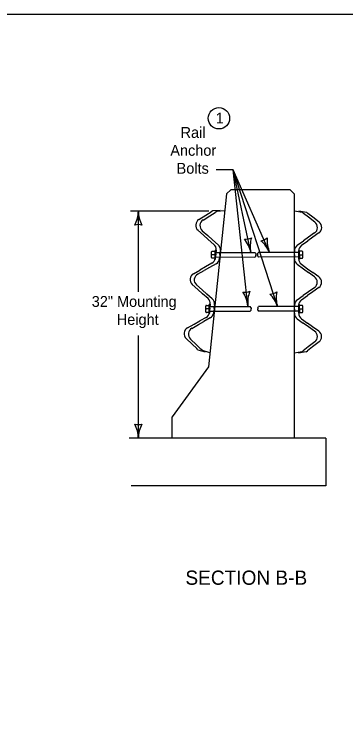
# Model space of a CAD drawing. Extents: x 10028 to 81668, y 3581 to 11018.
# Drawn here: x 14485 to 14950, y 8948 to 9944 of the extents above; entities that cross this region are included whole.
import ezdxf

# ---------------------------------------------------------------- set-up
doc = ezdxf.new("R2010")
doc.units = 0
for name, color, linetype in [('dsnCellsNorthArrow', 7, 'Continuous'), ('dsnTextTabulation', 7, 'Continuous'), ('Level 9', 7, 'Continuous'), ('SheetBorder', 7, 'Continuous')]:
    doc.layers.add(name, color=color, linetype=linetype)

msp = doc.modelspace()

# ---------------------------------------------------------------- linework, layer by layer
at = {"layer": 'dsnCellsNorthArrow'}
for p, q in [((14788.88, 9697.25), (14782.39, 9691.57)), ((14872.02, 9697.25), (14788.88, 9697.25)), ((14877.77, 9691.27), (14872.02, 9697.25)), ((14782.39, 9691.57), (14757.16, 9448.63)), ((14877.77, 9348.63), (14877.77, 9691.27)), ((14757.16, 9448.63), (14706.58, 9378.63)), ((14706.58, 9348.63), (14706.58, 9378.63))]:
    msp.add_line(p, q, dxfattribs=at)
at = {"layer": 'dsnTextTabulation'}
for p, q in [((14791.77, 9725.56), (14768.17, 9725.56)), ((14812.49, 9534.46), (14791.77, 9725.56)), ((14816.68, 9609.51), (14791.77, 9725.56)), ((14854.17, 9533.33), (14791.77, 9725.56)), ((14843.09, 9609.5), (14791.77, 9725.56)), ((14647.84, 9667.77), (14757.73, 9667.77)), ((14753.37, 9661.57), (14760.95, 9666.28)), ((14763.19, 9667.67), (14760.95, 9666.28)), ((14773.91, 9668.41), (14763.19, 9667.67)), ((14769.16, 9667.03), (14766.92, 9665.64)), ((14779.87, 9667.77), (14769.16, 9667.03)), ((14878.05, 9667.77), (14888.63, 9665.89)), ((14884.05, 9667.77), (14894.63, 9665.89)), ((14658.91, 9554.01), (14658.91, 9661.87)), ((14743.84, 9655.65), (14753.37, 9661.57)), ((14749.8, 9655.01), (14759.34, 9660.93)), ((14759.34, 9660.93), (14766.92, 9665.64)), ((14888.63, 9665.89), (14890.71, 9664.26)), ((14897.74, 9658.78), (14890.71, 9664.26)), ((14894.63, 9665.89), (14896.71, 9664.26)), ((14903.74, 9658.78), (14896.71, 9664.26)), ((14906.59, 9651.87), (14897.74, 9658.78)), ((14912.59, 9651.87), (14903.74, 9658.78)), ((14742.56, 9640.61), (14750.31, 9633.75)), ((14748.53, 9639.96), (14756.28, 9633.1)), ((14906.25, 9636.78), (14897.81, 9630.78)), ((14912.25, 9636.78), (14903.81, 9630.78)), ((14750.31, 9633.75), (14756.98, 9627.84)), ((14756.28, 9633.1), (14762.95, 9627.2)), ((14764.94, 9620.79), (14756.98, 9627.84)), ((14770.91, 9620.15), (14762.95, 9627.2)), ((14897.81, 9630.78), (14890.55, 9625.62)), ((14903.81, 9630.78), (14896.55, 9625.62)), ((14881.88, 9619.47), (14890.55, 9625.62)), ((14887.88, 9619.47), (14896.55, 9625.62)), ((14767.5, 9607.28), (14767.11, 9603.54)), ((14767.48, 9607.14), (14767.89, 9611.01)), ((14768.07, 9612.76), (14767.89, 9611.01)), ((14773.46, 9606.64), (14773.07, 9602.9)), ((14773.45, 9606.5), (14773.85, 9610.37)), ((14774.04, 9612.12), (14773.85, 9610.37)), ((14877.9, 9606.3), (14877.89, 9602.55)), ((14877.9, 9606.16), (14877.91, 9610.05)), ((14877.91, 9611.82), (14877.91, 9610.05)), ((14883.9, 9606.3), (14883.89, 9602.55)), ((14883.9, 9606.16), (14883.91, 9610.05)), ((14883.91, 9611.82), (14883.91, 9610.05)), ((14766.89, 9601.51), (14767.11, 9603.54)), ((14772.86, 9600.87), (14773.07, 9602.9)), ((14877.88, 9600.5), (14877.89, 9602.55)), ((14883.88, 9600.5), (14883.89, 9602.55)), ((14752.94, 9589.07), (14745.19, 9584.68)), ((14758.91, 9588.43), (14751.15, 9584.04)), ((14762.16, 9594.3), (14752.94, 9589.07)), ((14768.13, 9593.66), (14758.91, 9588.43)), ((14881.81, 9592.83), (14890.43, 9586.65)), ((14887.81, 9592.83), (14896.43, 9586.65)), ((14890.43, 9586.65), (14897.66, 9581.45)), ((14896.43, 9586.65), (14903.66, 9581.45)), ((14736.16, 9579.56), (14745.19, 9584.68)), ((14742.13, 9578.92), (14751.15, 9584.04)), ((14906.09, 9575.4), (14897.66, 9581.45)), ((14912.09, 9575.4), (14903.66, 9581.45)), ((14734.31, 9564.56), (14742.34, 9557.46)), ((14740.28, 9563.92), (14748.3, 9556.81)), ((14742.34, 9557.46), (14749.01, 9551.55)), ((14748.3, 9556.81), (14754.97, 9550.91)), ((14906.33, 9560.28), (14897.59, 9554.08)), ((14912.33, 9560.28), (14903.59, 9554.08)), ((14756.69, 9544.75), (14749.01, 9551.55)), ((14762.66, 9544.11), (14754.97, 9550.91)), ((14881.96, 9542.98), (14890.33, 9548.92)), ((14887.96, 9542.98), (14896.33, 9548.92)), ((14897.59, 9554.08), (14890.33, 9548.92)), ((14903.59, 9554.08), (14896.33, 9548.92)), ((14759.82, 9536.72), (14759.66, 9535.14)), ((14758.64, 9525.46), (14758.88, 9527.67)), ((14759.27, 9531.41), (14758.88, 9527.67)), ((14759.27, 9531.41), (14759.66, 9535.14)), ((14764.61, 9524.82), (14764.84, 9527.03)), ((14765.23, 9530.76), (14764.84, 9527.03)), ((14765.23, 9530.76), (14765.62, 9534.5)), ((14765.79, 9536.07), (14765.62, 9534.5)), ((14877.98, 9529.98), (14877.97, 9526.23)), ((14877.98, 9529.98), (14877.99, 9533.74)), ((14877.99, 9535.32), (14877.99, 9533.74)), ((14883.98, 9529.98), (14883.97, 9526.23)), ((14883.98, 9529.98), (14883.99, 9533.74)), ((14883.99, 9535.32), (14883.99, 9533.74)), ((14753.91, 9518.26), (14744.98, 9513.19)), ((14759.88, 9517.61), (14750.95, 9512.55)), ((14877.96, 9524.01), (14877.97, 9526.23)), ((14883.96, 9524.01), (14883.97, 9526.23)), ((14727.91, 9503.52), (14737.23, 9508.8)), ((14733.88, 9502.88), (14743.2, 9508.16)), ((14737.23, 9508.8), (14744.98, 9513.19)), ((14743.2, 9508.16), (14750.95, 9512.55)), ((14881.89, 9516.34), (14890.23, 9510.35)), ((14887.89, 9516.34), (14896.23, 9510.35)), ((14897.47, 9505.15), (14890.23, 9510.35)), ((14903.47, 9505.15), (14896.23, 9510.35)), ((14906.17, 9498.91), (14897.47, 9505.15)), ((14912.17, 9498.91), (14903.47, 9505.15)), ((14658.91, 9348.52), (14658.91, 9493)), ((14726.04, 9488.53), (14734.38, 9480.53)), ((14732, 9487.89), (14740.35, 9479.89)), ((14734.38, 9480.53), (14740.82, 9474.36)), ((14740.35, 9479.89), (14746.79, 9473.72)), ((14897.28, 9476.74), (14890.22, 9471.29)), ((14903.28, 9476.74), (14896.22, 9471.29)), ((14906.44, 9483.81), (14897.28, 9476.74)), ((14912.44, 9483.81), (14903.28, 9476.74)), ((14742.48, 9472.76), (14740.82, 9474.36)), ((14742.48, 9472.76), (14752.81, 9469.82)), ((14748.45, 9472.12), (14746.79, 9473.72)), ((14748.45, 9472.12), (14758.78, 9469.17)), ((14888.4, 9469.89), (14877.82, 9468.06)), ((14894.4, 9469.89), (14883.82, 9468.06)), ((14888.4, 9469.89), (14890.22, 9471.29)), ((14894.4, 9469.89), (14896.22, 9471.29))]:
    msp.add_line(p, q, dxfattribs=at)
msp.add_circle((14771.88, 9797.84), 15, dxfattribs=at)
for centre, radius, start, end in [((14616.41, 9667.77), 42.5, 331.92751, 360), ((14701.41, 9667.77), 42.5, 180, 208.07249), ((14658.91, 9632.13), 16.42, 72.26665, 107.73335), ((14809.6, 9644.43), 16.42, 263.73128, 299.19799), ((14775.03, 9601.06), 42.5, 11.46463, 39.53712), ((14858.33, 9617.96), 42.5, 163.39214, 191.46463), ((14829.05, 9642.25), 16.42, 275.46967, 310.93637), ((14882.15, 9626.24), 42.5, 175.13053, 203.20302), ((14804.03, 9592.75), 42.5, 23.20302, 51.27551), ((14809.05, 9569.93), 16.42, 257.8046, 293.2713), ((14770.19, 9530.36), 42.5, 5.53795, 33.61044), ((14854.79, 9538.56), 42.5, 157.46546, 185.53795), ((14843.55, 9567.35), 16.42, 269.60048, 305.06718), ((14813.6, 9520.67), 42.5, 17.33383, 45.40632), ((14894.74, 9545.99), 42.5, 169.26134, 197.33383), ((14658.91, 9384.16), 16.42, 252.26665, 287.73335), ((14616.41, 9348.52), 42.5, 360, 28.07249), ((14701.41, 9348.52), 42.5, 151.92751, 180)]:
    msp.add_arc(centre, radius, start, end, dxfattribs=at)
for centre, major_axis, start_param, end_param in [((14748.86, 9647.65), (9.43, -0.99), 2.229659, 4.096128), ((14754.82, 9647.01), (9.43, -0.99), 2.229659, 4.096128), ((14900.74, 9644.45), (-9.48, 0.02), 2.187057, 4.053527), ((14906.74, 9644.45), (-9.48, 0.02), 2.187057, 4.053527), ((14758.65, 9613.75), (9.43, -0.99), 0, 0.954538), ((14764.61, 9613.11), (9.43, -0.99), 0, 0.954538), ((14887.39, 9611.79), (-9.48, 0.02), 5.328647, 6.283185), ((14893.39, 9611.79), (-9.48, 0.02), 5.328647, 6.283185), ((14757.47, 9602.5), (-9.43, 0.99), 2.187055, 3.141593), ((14763.43, 9601.86), (-9.43, 0.99), 2.187055, 3.141593), ((14887.36, 9600.48), (9.48, -0.02), 3.141593, 4.096131), ((14893.36, 9600.48), (9.48, -0.02), 3.141593, 4.096131), ((14740.86, 9571.37), (-9.43, 0.99), 5.32865, 7.195119), ((14746.83, 9570.73), (-9.43, 0.99), 5.32865, 7.195119), ((14900.55, 9567.75), (9.48, -0.02), 5.371251, 7.237721), ((14906.55, 9567.75), (9.48, -0.02), 5.371251, 7.237721), ((14750.4, 9537.7), (9.43, -0.99), 0, 0.954538), ((14756.36, 9537.06), (9.43, -0.99), 0, 0.954538), ((14887.47, 9535.3), (-9.48, 0.02), 5.328647, 6.283185), ((14893.47, 9535.3), (-9.48, 0.02), 5.328647, 6.283185), ((14749.22, 9526.45), (-9.43, 0.99), 2.187055, 3.141593), ((14755.18, 9525.81), (-9.43, 0.99), 2.187055, 3.141593), ((14887.44, 9523.98), (9.48, -0.02), 3.141593, 4.096131), ((14893.44, 9523.98), (9.48, -0.02), 3.141593, 4.096131), ((14732.61, 9495.32), (-9.43, 0.99), 5.32865, 7.195119), ((14738.58, 9494.68), (-9.43, 0.99), 5.32865, 7.195119), ((14900.63, 9491.26), (9.48, -0.02), 5.371251, 7.237721), ((14906.63, 9491.26), (9.48, -0.02), 5.371251, 7.237721)]:
    msp.add_ellipse(centre, major_axis=major_axis, ratio=0.994906, start_param=start_param, end_param=end_param, dxfattribs=at)
at = {"layer": 'Level 9'}
for p, q in [((14761.67, 9605.44), (14761.67, 9610.3)), ((14766.47, 9606.3), (14762.63, 9606.3)), ((14762.64, 9611.16), (14766.48, 9611.16)), ((14766.47, 9606.3), (14766.48, 9612.38)), ((14766.47, 9601.44), (14766.48, 9611.16)), ((14766.47, 9606.3), (14766.47, 9600.23)), ((14767.38, 9612.38), (14766.48, 9612.38)), ((14767.37, 9600.23), (14767.38, 9612.38)), ((14767.37, 9606.3), (14767.37, 9609.54)), ((14767.74, 9609.54), (14822.47, 9609.5)), ((14823.65, 9607.87), (14822.48, 9609.49)), ((14823.65, 9607.87), (14823.65, 9606.25)), ((14823.65, 9604.63), (14823.65, 9606.25)), ((14826.3, 9607.87), (14827.47, 9609.49)), ((14826.3, 9607.87), (14826.3, 9606.25)), ((14826.3, 9604.63), (14826.3, 9606.25)), ((14883.89, 9609.54), (14827.47, 9609.49)), ((14883.9, 9600.23), (14883.89, 9612.38)), ((14883.89, 9612.38), (14884.79, 9612.38)), ((14883.9, 9606.3), (14883.89, 9609.54)), ((14884.8, 9606.3), (14884.79, 9612.38)), ((14884.8, 9601.44), (14884.79, 9611.16)), ((14888.63, 9611.16), (14884.79, 9611.16)), ((14884.8, 9606.3), (14884.8, 9600.23)), ((14884.8, 9606.3), (14888.64, 9606.3)), ((14889.6, 9605.44), (14889.59, 9610.3)), ((14761.67, 9602.31), (14761.67, 9605.44)), ((14766.47, 9601.44), (14762.63, 9601.44)), ((14766.47, 9600.23), (14767.37, 9600.23)), ((14767.06, 9603.06), (14822.52, 9603.02)), ((14823.65, 9604.63), (14822.47, 9603.01)), ((14826.3, 9604.63), (14827.48, 9603.01)), ((14883.9, 9603.06), (14827.48, 9603.01)), ((14884.8, 9600.23), (14883.9, 9600.23)), ((14884.8, 9601.44), (14888.64, 9601.44)), ((14889.6, 9602.31), (14889.6, 9605.44)), ((14753.43, 9526.13), (14753.44, 9529.27)), ((14753.44, 9529.27), (14753.44, 9534.13)), ((14754.4, 9534.99), (14758.24, 9534.99)), ((14758.24, 9530.13), (14754.4, 9530.13)), ((14758.23, 9525.27), (14758.24, 9534.99)), ((14758.24, 9530.13), (14758.23, 9524.05)), ((14758.24, 9530.13), (14758.24, 9536.2)), ((14759.14, 9536.2), (14758.24, 9536.2)), ((14758.79, 9526.9), (14815.88, 9526.85)), ((14759.13, 9524.05), (14759.14, 9536.2)), ((14759.14, 9530.13), (14759.14, 9533.37)), ((14759.47, 9533.38), (14815.88, 9533.33)), ((14817.06, 9531.71), (14815.88, 9533.33)), ((14817.06, 9528.47), (14815.88, 9526.85)), ((14817.06, 9531.71), (14817.06, 9530.09)), ((14817.06, 9528.47), (14817.06, 9530.09)), ((14826.38, 9531.7), (14827.55, 9533.32)), ((14826.38, 9531.7), (14826.38, 9530.08)), ((14826.38, 9528.46), (14826.38, 9530.08)), ((14826.38, 9528.46), (14827.56, 9526.84)), ((14883.97, 9533.37), (14827.55, 9533.32)), ((14883.98, 9526.89), (14827.56, 9526.84)), ((14883.98, 9524.05), (14883.97, 9536.2)), ((14883.97, 9536.2), (14884.87, 9536.2)), ((14883.98, 9530.13), (14883.97, 9533.37)), ((14884.88, 9530.13), (14884.87, 9536.2)), ((14884.88, 9525.27), (14884.87, 9534.99)), ((14888.71, 9534.99), (14884.87, 9534.99)), ((14884.88, 9530.13), (14884.88, 9524.05)), ((14884.88, 9530.13), (14888.72, 9530.13)), ((14889.68, 9529.27), (14889.67, 9534.13)), ((14889.68, 9526.13), (14889.68, 9529.27)), ((14758.23, 9525.27), (14754.39, 9525.27)), ((14758.23, 9524.05), (14759.13, 9524.05)), ((14884.88, 9524.05), (14883.98, 9524.05)), ((14884.88, 9525.27), (14888.72, 9525.27)), ((14921.98, 9348.52), (14646.13, 9348.52)), ((14921.98, 9348.52), (14921.98, 9281.53)), ((14921.98, 9281.53), (14648.95, 9281.53))]:
    msp.add_line(p, q, dxfattribs=at)
for centre, major_axis, start_param, end_param in [((14762.63, 9610.3), (-0.96, 0.001), 4.712389, 6.283185), ((14762.63, 9607.17), (-0.96, 0.001), 0, 1.570796), ((14762.63, 9605.44), (-0.96, 0.001), 4.712389, 6.283185), ((14888.63, 9610.3), (-0.96, -0.001), 3.141593, 4.712389), ((14888.64, 9607.17), (-0.96, -0.001), 1.570796, 3.141593), ((14888.64, 9605.44), (-0.96, -0.001), 3.141593, 4.712389), ((14762.63, 9602.31), (-0.96, 0.001), 6.283185, 7.853982), ((14888.64, 9602.31), (-0.96, -0.001), 1.570796, 3.141593), ((14754.4, 9534.13), (-0.96, 0.001), 4.712389, 6.283185), ((14754.4, 9530.99), (-0.96, 0.001), 0, 1.570796), ((14754.4, 9529.27), (-0.96, 0.001), 4.712389, 6.283185), ((14888.71, 9534.13), (-0.96, -0.001), 3.141593, 4.712389), ((14888.72, 9530.99), (-0.96, -0.001), 1.570796, 3.141593), ((14888.72, 9529.27), (-0.96, -0.001), 3.141593, 4.712389), ((14754.39, 9526.13), (-0.96, 0.001), 6.283185, 7.853982), ((14888.72, 9526.13), (-0.96, -0.001), 1.570796, 3.141593)]:
    msp.add_ellipse(centre, major_axis=major_axis, ratio=0.899999, start_param=start_param, end_param=end_param, dxfattribs=at)
at = {"layer": 'SheetBorder'}
msp.add_lwpolyline([(13732.52, 9944.02), (16867.53, 9944.02), (16867.53, 7924.02), (13732.52, 7924.02)], close=True, dxfattribs=at)

# ---------------------------------------------------------------- texts
at = {"layer": 'dsnCellsNorthArrow'}
for s, height, p in [('Rail', 15.2, (14718.13, 9770.38)), ('Anchor', 15.2, (14703.76, 9745.18)), ('Bolts', 15.2, (14712.6, 9719.98)), ('32" Mounting', 15.2, (14593.51, 9532.99)), ('Height', 15.2, (14628.62, 9507.79)), ('SECTION B-B', 20, (14724.95, 9142.74))]:
    msp.add_text(s, height=height, dxfattribs=at).set_placement(p)
at = {"layer": 'dsnTextTabulation'}
msp.add_text('1', height=15.2, dxfattribs=at).set_placement((14767.51, 9790.54))

doc.saveas('drawing.dxf')
